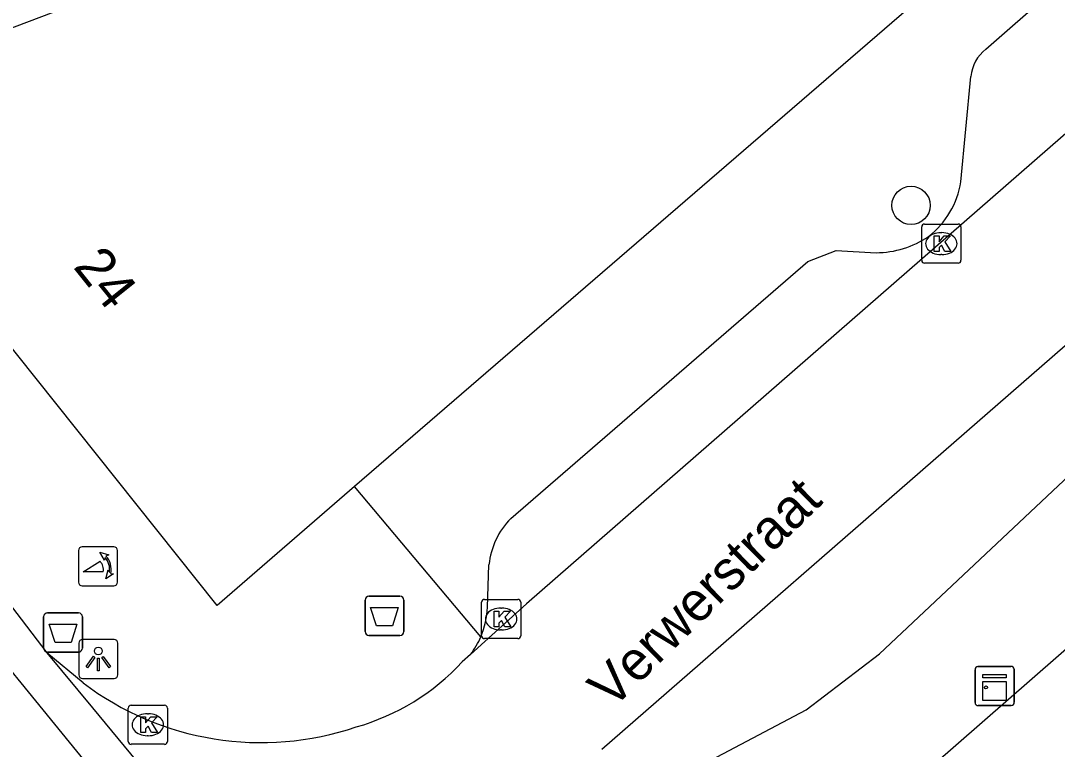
# Model space of a CAD drawing. Extents: x 160861 to 161308, y 384024 to 384878.
# Drawn here: x 160965.47 to 160991.93, y 384577.71 to 384596.31 of the extents above; entities that cross this region are included whole.
import ezdxf

# ---------------------------------------------------------------- set-up
doc = ezdxf.new("R2010")
doc.units = 0
for name, color, linetype in [('IMGEO_Afvalbak', 7, 'Continuous'), ('IMGEO_Boom', 7, 'Continuous'), ('IMGEO_Fietspad_gesloten', 7, 'Continuous'), ('IMGEO_Fietspad_open', 7, 'Continuous'), ('IMGEO_Kast', 7, 'Continuous'), ('IMGEO_Kolk', 7, 'Continuous'), ('IMGEO_Lichtpunt', 7, 'Continuous'), ('IMGEO_Openbare_ruimte_label', 7, 'Continuous'), ('IMGEO_Pand', 7, 'Continuous'), ('IMGEO_Pand_nummerreeks', 7, 'Continuous'), ('IMGEO_Poller', 7, 'Continuous'), ('IMGEO_Rijbaan_lokaal_gesloten', 7, 'Continuous'), ('IMGEO_Voetpad_open', 7, 'Continuous')]:
    doc.layers.add(name, color=color, linetype=linetype)

msp = doc.modelspace()

# ---------------------------------------------------------------- linework, layer by layer
at = {"layer": 'IMGEO_Afvalbak'}
for p, q in [((160974.262, 384580.719), (160974.262, 384581.519)), ((160974.262, 384581.519), (160974.262, 384580.719)), ((160974.362, 384581.619), (160975.152, 384581.619)), ((160975.152, 384581.619), (160974.362, 384581.619)), ((160975.252, 384581.519), (160975.252, 384580.719)), ((160975.252, 384580.719), (160975.252, 384581.519)), ((160966.158, 384581.195), (160966.948, 384581.195)), ((160966.948, 384581.195), (160966.158, 384581.195)), ((160966.058, 384580.295), (160966.058, 384581.095)), ((160966.058, 384581.095), (160966.058, 384580.295)), ((160967.048, 384581.095), (160967.048, 384580.295)), ((160967.048, 384580.295), (160967.048, 384581.095)), ((160975.152, 384580.619), (160974.362, 384580.619)), ((160974.362, 384580.619), (160975.152, 384580.619)), ((160966.948, 384580.195), (160966.158, 384580.195)), ((160966.158, 384580.195), (160966.948, 384580.195))]:
    msp.add_line(p, q, dxfattribs=at)
for points in [[(160974.405, 384581.333), (160975.109, 384581.333), (160974.96, 384580.863), (160974.554, 384580.863), (160974.405, 384581.333)], [(160966.201, 384580.909), (160966.905, 384580.909), (160966.756, 384580.439), (160966.35, 384580.439), (160966.201, 384580.909)]]:
    msp.add_lwpolyline(points, dxfattribs=at)
for centre, start, end in [((160974.362, 384581.519), 90, 180), ((160974.362, 384581.519), 90, 180), ((160975.152, 384581.519), 0, 90), ((160975.152, 384581.519), 360, 90), ((160966.158, 384581.095), 90, 180), ((160966.158, 384581.095), 90, 180), ((160966.948, 384581.095), 0, 90), ((160966.948, 384581.095), 360, 90), ((160974.362, 384580.719), 180, 270), ((160974.362, 384580.719), 180, 270), ((160975.152, 384580.719), 270, 0), ((160975.152, 384580.719), 270, 0), ((160966.158, 384580.295), 180, 270), ((160966.158, 384580.295), 180, 270), ((160966.948, 384580.295), 270, 0), ((160966.948, 384580.295), 270, 0)]:
    msp.add_arc(centre, 0.1, start, end, dxfattribs=at)
at = {"layer": 'IMGEO_Boom'}
msp.add_circle((160988.2, 384591.593), 0.489, dxfattribs=at)
at = {"layer": 'IMGEO_Fietspad_gesloten'}
msp.add_lwpolyline([(160978.487, 384563.462), (160966.529, 384578.127), (160965.859, 384578.948), (160964.841, 384580.196), (160959.37, 384587.387)], dxfattribs=at)
at = {"layer": 'IMGEO_Fietspad_open'}
msp.add_lwpolyline([(160960.339, 384587.77), (160966.142, 384580.179)], dxfattribs=at)
at = {"layer": 'IMGEO_Kast'}
for p, q in [((160989.833, 384578.904), (160989.833, 384579.745)), ((160989.833, 384579.745), (160989.833, 384578.904)), ((160989.908, 384579.829), (160990.749, 384579.829)), ((160990.749, 384579.829), (160989.908, 384579.829)), ((160990.833, 384579.754), (160990.833, 384578.913)), ((160990.833, 384578.913), (160990.833, 384579.754)), ((160990.758, 384578.829), (160989.917, 384578.829)), ((160989.917, 384578.829), (160990.758, 384578.829))]:
    msp.add_line(p, q, dxfattribs=at)
for points in [[(160990.028, 384579.619), (160990.628, 384579.619), (160990.628, 384579.534), (160990.028, 384579.534), (160990.028, 384579.619)], [(160990.028, 384579.444), (160990.628, 384579.444), (160990.628, 384578.955), (160990.028, 384578.955), (160990.028, 384579.444)]]:
    msp.add_lwpolyline(points, dxfattribs=at)
msp.add_circle((160990.112, 384579.293), 0.0377, dxfattribs=at)
for centre, start, end in [((160989.911, 384579.751), 92.4484, 184.2845), ((160989.911, 384579.751), 92.4484, 184.2845), ((160990.755, 384579.751), 2.4484, 94.2845), ((160990.755, 384579.751), 2.4484, 94.2845), ((160989.911, 384578.907), 182.4484, 274.2845), ((160989.911, 384578.907), 182.4484, 274.2845), ((160990.755, 384578.907), 272.4484, 4.2845), ((160990.755, 384578.907), 272.4484, 4.2845)]:
    msp.add_arc(centre, 0.0779, start, end, dxfattribs=at)
at = {"layer": 'IMGEO_Kolk'}
for p, q in [((160988.472, 384590.192), (160988.472, 384591.044)), ((160988.547, 384591.118), (160989.399, 384591.118)), ((160989.473, 384591.044), (160989.473, 384590.192)), ((160988.96, 384590.898), (160988.985, 384590.898)), ((160988.983, 384590.338), (160988.958, 384590.338)), ((160989.399, 384590.118), (160988.547, 384590.118)), ((160977.236, 384580.612), (160977.236, 384581.464)), ((160977.311, 384581.538), (160978.163, 384581.538)), ((160978.237, 384581.464), (160978.237, 384580.612)), ((160977.724, 384581.318), (160977.749, 384581.318)), ((160977.747, 384580.758), (160977.722, 384580.758)), ((160978.163, 384580.538), (160977.311, 384580.538)), ((160968.292, 384578.84), (160969.144, 384578.84)), ((160968.217, 384577.914), (160968.217, 384578.766)), ((160968.705, 384578.62), (160968.73, 384578.62)), ((160969.218, 384578.766), (160969.218, 384577.914)), ((160968.728, 384578.06), (160968.703, 384578.06)), ((160969.144, 384577.84), (160968.292, 384577.84))]:
    msp.add_line(p, q, dxfattribs=at)
for points in [[(160988.472, 384590.192), (160988.472, 384591.044)], [(160988.547, 384591.118), (160989.399, 384591.118)], [(160989.473, 384591.044), (160989.473, 384590.192)], [(160988.793, 384590.818), (160988.916, 384590.818), (160988.916, 384590.667), (160989.046, 384590.818), (160989.21, 384590.818), (160989.064, 384590.667), (160989.217, 384590.418), (160989.065, 384590.418), (160988.98, 384590.582), (160988.916, 384590.515), (160988.916, 384590.418), (160988.793, 384590.418), (160988.793, 384590.818)], [(160989.399, 384590.118), (160988.547, 384590.118)], [(160977.236, 384580.612), (160977.236, 384581.464)], [(160977.311, 384581.538), (160978.163, 384581.538)], [(160978.237, 384581.464), (160978.237, 384580.612)], [(160977.557, 384581.238), (160977.68, 384581.238), (160977.68, 384581.087), (160977.81, 384581.238), (160977.974, 384581.238), (160977.828, 384581.087), (160977.981, 384580.838), (160977.829, 384580.838), (160977.744, 384581.002), (160977.68, 384580.935), (160977.68, 384580.838), (160977.557, 384580.838), (160977.557, 384581.238)], [(160978.163, 384580.538), (160977.311, 384580.538)], [(160968.292, 384578.84), (160969.144, 384578.84)], [(160968.217, 384577.914), (160968.217, 384578.766)], [(160968.538, 384578.54), (160968.661, 384578.54), (160968.661, 384578.389), (160968.791, 384578.54), (160968.955, 384578.54), (160968.809, 384578.389), (160968.962, 384578.14), (160968.81, 384578.14), (160968.725, 384578.304), (160968.661, 384578.237), (160968.661, 384578.14), (160968.538, 384578.14), (160968.538, 384578.54)], [(160969.218, 384578.766), (160969.218, 384577.914)], [(160969.144, 384577.84), (160968.292, 384577.84)]]:
    msp.add_lwpolyline(points, dxfattribs=at)
for centre, start, end in [((160988.549, 384591.042), 91.552, 178.448), ((160988.549, 384591.042), 91.552, 178.448), ((160989.397, 384591.042), 1.552, 88.448), ((160989.397, 384591.042), 1.552, 88.448), ((160988.549, 384590.194), 181.552, 268.448), ((160988.549, 384590.194), 181.552, 268.448), ((160989.397, 384590.194), 271.552, 358.448), ((160989.397, 384590.194), 271.552, 358.448), ((160977.313, 384581.462), 91.552, 178.448), ((160977.313, 384581.462), 91.552, 178.448), ((160978.161, 384581.462), 1.552, 88.448), ((160978.161, 384581.462), 1.552, 88.448), ((160977.313, 384580.614), 181.552, 268.448), ((160977.313, 384580.614), 181.552, 268.448), ((160978.161, 384580.614), 271.552, 358.448), ((160978.161, 384580.614), 271.552, 358.448), ((160968.294, 384578.764), 91.552, 178.448), ((160968.294, 384578.764), 91.552, 178.448), ((160969.142, 384578.764), 1.552, 88.448), ((160969.142, 384578.764), 1.552, 88.448), ((160968.294, 384577.916), 181.552, 268.448), ((160968.294, 384577.916), 181.552, 268.448), ((160969.142, 384577.916), 271.552, 358.448), ((160969.142, 384577.916), 271.552, 358.448)]:
    msp.add_arc(centre, 0.0765, start, end, dxfattribs=at)
for centre, major_axis, ratio, start_param, end_param in [((160988.959, 384590.618), (-0.387, 0.002), 0.722429, 4.712389, 7.853982), ((160988.984, 384590.618), (-0.39, 0.002), 0.717154, 1.570796, 4.712389), ((160977.723, 384581.038), (-0.387, 0.002), 0.722429, 4.712389, 7.853982), ((160977.748, 384581.038), (-0.39, 0.002), 0.717154, 1.570796, 4.712389), ((160968.704, 384578.34), (-0.387, 0.002), 0.722429, 4.712389, 7.853982), ((160968.729, 384578.34), (-0.39, 0.002), 0.717154, 1.570796, 4.712389)]:
    msp.add_ellipse(centre, major_axis=major_axis, ratio=ratio, start_param=start_param, end_param=end_param, dxfattribs=at)
at = {"layer": 'IMGEO_Lichtpunt'}
for p, q in [((160966.955, 384580.422), (160966.955, 384579.615)), ((160966.955, 384580.422), (160966.955, 384579.615)), ((160967.857, 384580.517), (160967.049, 384580.517)), ((160967.857, 384580.517), (160967.049, 384580.517)), ((160967.951, 384579.615), (160967.951, 384580.422)), ((160967.951, 384579.615), (160967.951, 384580.422)), ((160967.049, 384579.521), (160967.857, 384579.521)), ((160967.049, 384579.521), (160967.857, 384579.521))]:
    msp.add_line(p, q, dxfattribs=at)
for points in [[(160967.329, 384580.086), (160967.368, 384580.058), (160967.18, 384579.796), (160967.142, 384579.823), (160967.329, 384580.086)], [(160967.431, 384580.038), (160967.478, 384580.038), (160967.478, 384579.716), (160967.431, 384579.716), (160967.431, 384580.038)], [(160967.541, 384580.058), (160967.579, 384580.085), (160967.766, 384579.823), (160967.727, 384579.795), (160967.541, 384580.058)]]:
    msp.add_lwpolyline(points, dxfattribs=at)
msp.add_circle((160967.454, 384580.22), 0.0994, dxfattribs=at)
for centre, start, end in [((160967.049, 384580.422), 90, 180), ((160967.049, 384580.422), 90, 180), ((160967.857, 384580.422), 0, 90), ((160967.857, 384580.422), 0, 90), ((160967.049, 384579.615), 180, 270), ((160967.049, 384579.615), 180, 270), ((160967.857, 384579.615), 270, 0), ((160967.857, 384579.615), 270, 360)]:
    msp.add_arc(centre, 0.0946, start, end, dxfattribs=at)
at = {"layer": 'IMGEO_Pand'}
for points in [[(160990.689, 384598.828), (160986.187, 384604.043), (160960.23, 384594.229)], [(160990.689, 384598.828), (160973.995, 384584.418)], [(160973.995, 384584.418), (160970.483, 384581.386), (160960.23, 384594.229)], [(160994.515, 384582.326), (160982.962, 384572.239), (160982.264, 384571.633)]]:
    msp.add_lwpolyline(points, dxfattribs=at)
at = {"layer": 'IMGEO_Poller'}
for p, q in [((160966.946, 384582.787), (160966.946, 384581.98)), ((160966.946, 384582.787), (160966.946, 384581.98)), ((160967.848, 384582.882), (160967.04, 384582.882)), ((160967.848, 384582.882), (160967.04, 384582.882)), ((160967.942, 384581.98), (160967.942, 384582.787)), ((160967.942, 384581.98), (160967.942, 384582.787)), ((160967.04, 384581.885), (160967.848, 384581.885)), ((160967.04, 384581.885), (160967.848, 384581.885))]:
    msp.add_line(p, q, dxfattribs=at)
for points in [[(160967.581, 384582.238), (160967.068, 384582.238), (160967.498, 384582.513)], [(160967.625, 384582.611), (160967.613, 384582.538), (160967.488, 384582.743)], [(160967.488, 384582.743), (160967.719, 384582.677), (160967.648, 384582.645)], [(160967.641, 384582.066), (160967.707, 384582.297), (160967.737, 384582.229)], [(160967.773, 384582.202), (160967.845, 384582.191), (160967.641, 384582.066)]]:
    msp.add_lwpolyline(points, dxfattribs=at)
for centre, radius, start, end in [((160967.04, 384582.787), 0.0946, 90, 180), ((160967.04, 384582.787), 0.0946, 90, 180), ((160967.848, 384582.787), 0.0946, 0, 90), ((160967.848, 384582.787), 0.0946, 0, 90), ((160967.253, 384582.288), 0.332, 351.3247, 42.4854), ((160967.267, 384582.298), 0.476, 351.7527, 41.1691), ((160967.267, 384582.298), 0.516, 349.3569, 42.2912), ((160967.04, 384581.98), 0.0946, 180, 270), ((160967.04, 384581.98), 0.0946, 180, 270), ((160967.848, 384581.98), 0.0946, 270, 0), ((160967.848, 384581.98), 0.0946, 270, 0)]:
    msp.add_arc(centre, radius, start, end, dxfattribs=at)
at = {"layer": 'IMGEO_Rijbaan_lokaal_gesloten'}
for points in [[(161041.622, 384637.072), (161035.757, 384631.338), (161021.935, 384619.355), (161000, 384600.273), (160978.384, 384581.429), (160977.321, 384580.465), (160976.957, 384580.135)], [(160980.308, 384577.714), (161000, 384594.865), (161038.406, 384628.276), (161045.97, 384635.823)], [(160966.142, 384580.179), (160967.308, 384578.769), (160978.54, 384565.18)], [(160967.063, 384579.409), (160966.142, 384580.179)], [(160976.957, 384580.135), (160976.745, 384579.943)]]:
    msp.add_lwpolyline(points, dxfattribs=at)
for centre, radius, start, end in [((160972.41, 384583.977), 5.922, 285.9389, 317.0588), ((160971.614, 384585.44), 7.556, 232.9605, 288.6936)]:
    msp.add_arc(centre, radius, start, end, dxfattribs=at)
at = {"layer": 'IMGEO_Voetpad_open'}
for points in [[(160990.109, 384595.581), (161000, 384604.231), (161000.794, 384604.925)], [(160989.47, 384592.198), (160989.729, 384594.881)], [(160977.982, 384583.606), (160985.567, 384590.158), (160986.284, 384590.445), (160987.307, 384590.386)], [(160979.156, 384575.363), (160985.52, 384578.721), (160987.397, 384580.151), (160993.662, 384586.043)], [(160977.218, 384580.587), (160973.995, 384584.418)], [(160977.387, 384581.339), (160977.426, 384582.422)]]:
    msp.add_lwpolyline(points, dxfattribs=at)
for centre, radius, start, end in [((160990.711, 384594.801), 0.985, 127.6506, 175.3581), ((160987.302, 384592.534), 2.194, 307.7789, 351.1898), ((160987.298, 384592.787), 2.401, 270.2103, 304.1515), ((160979.406, 384582.215), 1.991, 135.6677, 174.0233), ((160975.308, 384581.411), 2.081, 336.6607, 358.0076), ((160975.215, 384581.442), 2.178, 323.1147, 336.8781)]:
    msp.add_arc(centre, radius, start, end, dxfattribs=at)

# ---------------------------------------------------------------- texts
at = {"layer": 'IMGEO_Openbare_ruimte_label'}
msp.add_text('Verwerstraat', height=1, rotation=44.4327, dxfattribs=at).set_placement((160980.566, 384578.712))
at = {"layer": 'IMGEO_Pand_nummerreeks'}
msp.add_text('24', height=1, rotation=308.676, dxfattribs=at).set_placement((160966.792, 384590.021))

doc.saveas('drawing.dxf')
